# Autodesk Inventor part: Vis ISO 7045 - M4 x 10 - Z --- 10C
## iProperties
Created: 2011-01
Part Number: Vis ISO 7045 - M4 x 10 - Z --- 10C
Document SubType Name: Modeling
Designer: eric
Density: 1 g/cm^3
Mass: 0.210913 g
Surface Area: 2.697 cm^2
Volume: 0.210913 cm^3
Author: eric
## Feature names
1. Base1
